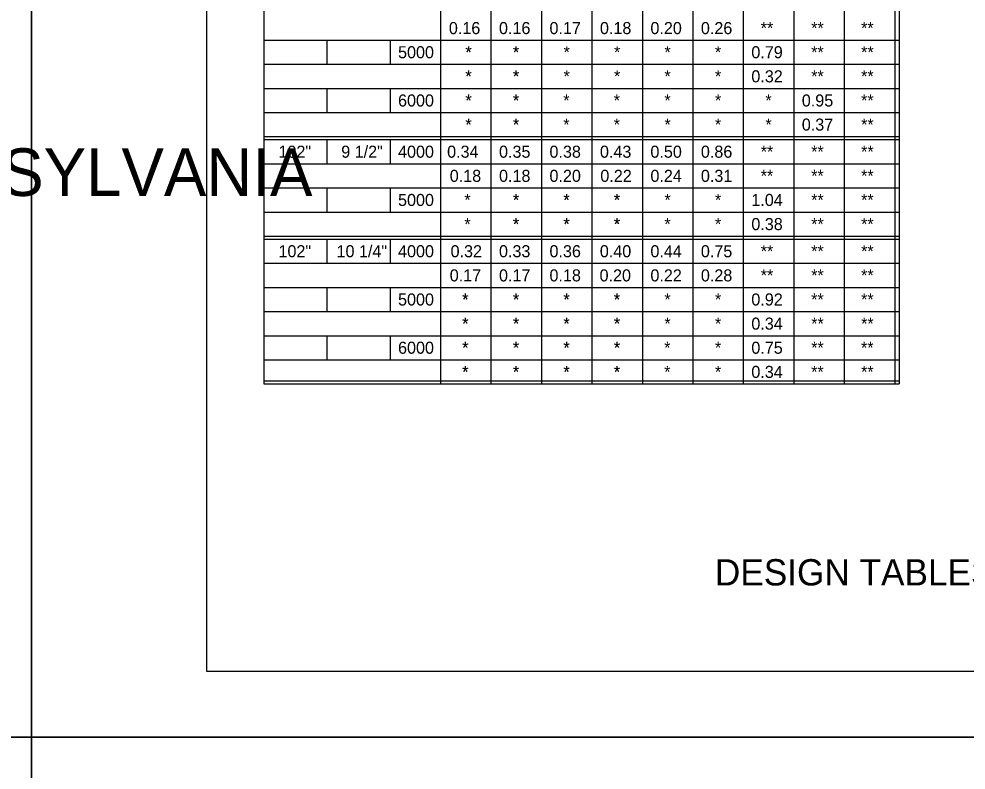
# Model space of a CAD drawing. Extents: x -22562 to -18409, y 3991 to 7171.
# Drawn here: x -20387.7 to -20171.7, y 5765.9 to 5937.3 of the extents above; entities that cross this region are included whole.
import ezdxf

# ---------------------------------------------------------------- set-up
doc = ezdxf.new("R2010")
doc.units = 0
for name, color, linetype in [('1', 7, 'Continuous'), ('2', 7, 'Continuous'), ('3', 7, 'Continuous'), ('4', 7, 'Continuous'), ('PLT-BNDY', 7, 'Continuous')]:
    doc.layers.add(name, color=color, linetype=linetype)

msp = doc.modelspace()

# ---------------------------------------------------------------- linework, layer by layer
at = {"layer": '2'}
for p, q in [((-20344.85, 5788.37), (-20344.85, 6352.37)), ((-20331.85, 6099.37), (-20331.85, 5853.98)), ((-20186.92, 6099.37), (-20186.92, 5853.98)), ((-20291.56, 6091.8), (-20291.56, 5853.98)), ((-20187.96, 6091.8), (-20187.96, 5853.98)), ((-20280.05, 6086.29), (-20280.05, 5853.98)), ((-20268.53, 6086.29), (-20268.53, 5853.98)), ((-20257.03, 6086.29), (-20257.03, 5853.98)), ((-20245.51, 6086.29), (-20245.51, 5853.98)), ((-20234, 6086.29), (-20234, 5853.98)), ((-20222.49, 6086.29), (-20222.49, 5853.98)), ((-20210.98, 6086.29), (-20210.98, 5853.98)), ((-20199.47, 6086.29), (-20199.47, 5853.98)), ((-20331.85, 5932.42), (-20186.92, 5932.42)), ((-20317.46, 5932.42), (-20317.46, 5926.92)), ((-20303.07, 5932.42), (-20303.07, 5926.92)), ((-20331.85, 5926.92), (-20186.92, 5926.92)), ((-20331.85, 5921.41), (-20186.92, 5921.41)), ((-20317.46, 5921.41), (-20317.46, 5915.91)), ((-20303.07, 5921.41), (-20303.07, 5915.91)), ((-20331.85, 5915.91), (-20186.92, 5915.91)), ((-20331.85, 5910.4), (-20186.92, 5910.4)), ((-20331.85, 5910.4), (-20186.92, 5910.4)), ((-20331.85, 5909.72), (-20186.92, 5909.72)), ((-20317.46, 5909.72), (-20317.46, 5904.21)), ((-20303.07, 5909.72), (-20303.07, 5904.21)), ((-20331.85, 5904.21), (-20186.92, 5904.21)), ((-20331.85, 5898.71), (-20186.92, 5898.71)), ((-20317.46, 5898.71), (-20317.46, 5893.2)), ((-20303.07, 5898.71), (-20303.07, 5893.2)), ((-20331.85, 5893.2), (-20186.92, 5893.2)), ((-20331.85, 5887.7), (-20186.92, 5887.7)), ((-20331.85, 5887.01), (-20186.92, 5887.01)), ((-20317.46, 5887.01), (-20317.46, 5881.5)), ((-20303.07, 5887.01), (-20303.07, 5881.5)), ((-20331.85, 5881.5), (-20186.92, 5881.5)), ((-20331.85, 5876), (-20186.92, 5876)), ((-20317.46, 5876), (-20317.46, 5870.49)), ((-20303.07, 5876), (-20303.07, 5870.49)), ((-20331.85, 5870.49), (-20186.92, 5870.49)), ((-20331.85, 5864.98), (-20186.92, 5864.98)), ((-20317.46, 5864.98), (-20317.46, 5859.48)), ((-20303.07, 5864.98), (-20303.07, 5859.48)), ((-20331.85, 5859.48), (-20186.92, 5859.48)), ((-20331.85, 5854.66), (-20186.92, 5854.66)), ((-20331.85, 5853.98), (-20186.92, 5853.98)), ((-19558.85, 5788.37), (-20344.85, 5788.37))]:
    msp.add_line(p, q, dxfattribs=at)
at = {"layer": 'PLT-BNDY'}
for points in [[(-21225.85, 6367.37), (-20384.85, 6367.37), (-20384.85, 5773.37), (-21225.85, 5773.37)], [(-20384.85, 6367.37), (-19543.85, 6367.37), (-19543.85, 5773.37), (-20384.85, 5773.37)], [(-21225.85, 5773.37), (-20384.85, 5773.37), (-20384.85, 5179.37), (-21225.85, 5179.37)], [(-20384.85, 5773.37), (-19543.85, 5773.37), (-19543.85, 5179.37), (-20384.85, 5179.37)]]:
    msp.add_lwpolyline(points, close=True, dxfattribs=at)

# ---------------------------------------------------------------- texts
at = {"layer": '1'}
for p in [(-20328.51, 5905.59), (-20328.51, 5882.88)]:
    msp.add_text('102"', height=2.751, dxfattribs=at).set_placement(p)
at = {"layer": '2'}
for s, height, p in [('COMMONWEALTH OF PENNSYLVANIA', 10.8525, (-20588.47, 5896.87)), ('DESIGN TABLES FOR CIRCULAR PIPES - TYPE A STANDARD INSTALLATION', 6, (-20228.97, 5807.99))]:
    msp.add_text(s, height=height, dxfattribs=at).set_placement(p)
at = {"layer": '3'}
for s, height, p in [('0.16', 2.753, (-20289.65, 5933.8)), ('0.16', 2.753, (-20278.22, 5933.8)), ('0.17', 2.753, (-20266.7, 5933.8)), ('0.18', 2.753, (-20255.19, 5933.8)), ('0.20', 2.753, (-20243.68, 5933.8)), ('0.26', 2.753, (-20232.17, 5933.8)), ('**', 2.753, (-20218.52, 5933.8)), ('**', 2.753, (-20207.01, 5933.8)), ('**', 2.751, (-20195.62, 5933.8)), ('*', 2.75, (-20285.91, 5928.29)), ('*', 2.75, (-20285.85, 5928.29)), ('*', 2.75, (-20275.07, 5928.29)), ('*', 2.75, (-20275.01, 5928.29)), ('*', 2.75, (-20263.49, 5928.29)), ('*', 2.75, (-20251.98, 5928.29)), ('*', 2.75, (-20240.48, 5928.29)), ('*', 2.75, (-20228.96, 5928.29)), ('0.79', 2.753, (-20220.66, 5928.29)), ('**', 2.753, (-20207.01, 5928.29)), ('**', 2.751, (-20195.62, 5928.29)), ('*', 2.75, (-20285.91, 5922.79)), ('*', 2.75, (-20285.85, 5922.79)), ('*', 2.75, (-20275.07, 5922.79)), ('*', 2.75, (-20275.01, 5922.79)), ('*', 2.75, (-20263.49, 5922.79)), ('*', 2.75, (-20251.98, 5922.79)), ('*', 2.75, (-20240.48, 5922.79)), ('*', 2.75, (-20228.96, 5922.79)), ('0.32', 2.753, (-20220.66, 5922.79)), ('**', 2.753, (-20207.01, 5922.79)), ('**', 2.751, (-20195.62, 5922.79)), ('*', 2.75, (-20285.91, 5917.28)), ('*', 2.75, (-20285.85, 5917.28)), ('*', 2.75, (-20275.07, 5917.28)), ('*', 2.75, (-20275.01, 5917.28)), ('*', 2.75, (-20263.56, 5917.28)), ('*', 2.75, (-20252.05, 5917.28)), ('*', 2.75, (-20240.48, 5917.28)), ('*', 2.75, (-20228.96, 5917.28)), ('*', 2.75, (-20217.45, 5917.28)), ('0.95', 2.753, (-20209.15, 5917.28)), ('**', 2.751, (-20195.62, 5917.28)), ('*', 2.75, (-20285.91, 5911.78)), ('*', 2.75, (-20285.85, 5911.78)), ('*', 2.75, (-20275.07, 5911.78)), ('*', 2.75, (-20275.01, 5911.78)), ('*', 2.75, (-20263.56, 5911.78)), ('*', 2.75, (-20252.05, 5911.78)), ('*', 2.75, (-20240.48, 5911.78)), ('*', 2.75, (-20228.96, 5911.78)), ('*', 2.75, (-20217.45, 5911.78)), ('0.37', 2.753, (-20209.15, 5911.78)), ('**', 2.751, (-20195.62, 5911.78)), ('0.34', 2.753, (-20290.05, 5905.59)), ('0.35', 2.753, (-20278.21, 5905.59)), ('0.38', 2.753, (-20266.7, 5905.59)), ('0.43', 2.753, (-20255.19, 5905.59)), ('0.50', 2.753, (-20243.68, 5905.59)), ('0.86', 2.753, (-20232.17, 5905.59)), ('**', 2.753, (-20218.52, 5905.59)), ('**', 2.753, (-20207.01, 5905.59)), ('**', 2.751, (-20195.62, 5905.59)), ('0.18', 2.753, (-20289.45, 5900.08)), ('0.18', 2.753, (-20278.21, 5900.08)), ('0.20', 2.753, (-20266.7, 5900.08)), ('0.22', 2.753, (-20255.1, 5900.08)), ('0.24', 2.753, (-20243.68, 5900.08)), ('0.31', 2.753, (-20232.17, 5900.08)), ('**', 2.753, (-20218.52, 5900.08)), ('**', 2.753, (-20207.01, 5900.08)), ('**', 2.751, (-20195.62, 5900.08)), ('1.04', 2.753, (-20220.66, 5894.58)), ('*', 2.75, (-20286.11, 5894.58)), ('*', 2.75, (-20275.07, 5894.58)), ('*', 2.75, (-20275.01, 5894.58)), ('*', 2.75, (-20263.56, 5894.58)), ('*', 2.75, (-20263.49, 5894.58)), ('*', 2.75, (-20252.05, 5894.58)), ('*', 2.75, (-20251.98, 5894.58)), ('*', 2.75, (-20240.48, 5894.58)), ('*', 2.75, (-20228.96, 5894.58)), ('**', 2.753, (-20207.01, 5894.58)), ('**', 2.751, (-20195.62, 5894.58)), ('*', 2.75, (-20286.11, 5889.05)), ('*', 2.75, (-20275.07, 5889.07)), ('*', 2.75, (-20275.01, 5889.07)), ('*', 2.75, (-20263.56, 5889.07)), ('*', 2.75, (-20263.49, 5889.07)), ('*', 2.75, (-20252.05, 5889.07)), ('*', 2.75, (-20251.98, 5889.07)), ('*', 2.75, (-20240.48, 5889.07)), ('*', 2.75, (-20228.96, 5889.07)), ('0.38', 2.753, (-20220.66, 5889.07)), ('**', 2.753, (-20207.01, 5889.07)), ('**', 2.751, (-20195.62, 5889.07)), ('0.32', 2.753, (-20289.26, 5882.88)), ('0.33', 2.753, (-20278.22, 5882.88)), ('0.36', 2.753, (-20266.7, 5882.88)), ('0.40', 2.753, (-20255.22, 5882.88)), ('0.44', 2.753, (-20243.68, 5882.88)), ('0.75', 2.753, (-20232.17, 5882.88)), ('**', 2.753, (-20218.52, 5882.88)), ('**', 2.753, (-20207.01, 5882.88)), ('**', 2.751, (-20195.62, 5882.87)), ('0.17', 2.753, (-20289.45, 5877.37)), ('0.17', 2.753, (-20278.21, 5877.37)), ('0.18', 2.753, (-20266.7, 5877.37)), ('0.20', 2.753, (-20255.28, 5877.37)), ('0.22', 2.753, (-20243.68, 5877.37)), ('0.28', 2.753, (-20232.17, 5877.37)), ('**', 2.753, (-20218.52, 5877.37)), ('**', 2.753, (-20207.01, 5877.37)), ('**', 2.751, (-20195.62, 5877.37)), ('*', 2.75, (-20286.64, 5871.87)), ('*', 2.75, (-20286.57, 5871.87)), ('*', 2.75, (-20275.07, 5871.87)), ('*', 2.75, (-20275.01, 5871.87)), ('*', 2.75, (-20263.56, 5871.87)), ('*', 2.75, (-20263.49, 5871.87)), ('*', 2.75, (-20252.05, 5871.87)), ('*', 2.75, (-20251.98, 5871.87)), ('*', 2.75, (-20240.48, 5871.87)), ('*', 2.75, (-20228.96, 5871.87)), ('0.92', 2.753, (-20220.66, 5871.87)), ('**', 2.753, (-20207.01, 5871.87)), ('**', 2.751, (-20195.62, 5871.87)), ('*', 2.75, (-20286.64, 5866.36)), ('*', 2.75, (-20286.57, 5866.36)), ('*', 2.75, (-20275.07, 5866.36)), ('*', 2.75, (-20275.01, 5866.36)), ('*', 2.75, (-20263.56, 5866.36)), ('*', 2.75, (-20263.49, 5866.36)), ('*', 2.75, (-20252.05, 5866.36)), ('*', 2.75, (-20251.98, 5866.36)), ('*', 2.75, (-20240.48, 5866.36)), ('*', 2.75, (-20228.96, 5866.36)), ('0.34', 2.753, (-20220.66, 5866.36)), ('**', 2.753, (-20207.01, 5866.36)), ('**', 2.751, (-20195.62, 5866.36)), ('*', 2.75, (-20286.64, 5860.86)), ('*', 2.75, (-20286.57, 5860.86)), ('*', 2.75, (-20275.07, 5860.86)), ('*', 2.75, (-20275.01, 5860.86)), ('*', 2.75, (-20263.56, 5860.86)), ('*', 2.75, (-20263.49, 5860.86)), ('*', 2.75, (-20252.05, 5860.86)), ('*', 2.75, (-20251.98, 5860.86)), ('*', 2.75, (-20240.54, 5860.86)), ('*', 2.75, (-20228.96, 5860.86)), ('0.75', 2.753, (-20220.66, 5860.86)), ('**', 2.753, (-20207.01, 5860.86)), ('*', 2.75, (-20286.64, 5855.35)), ('*', 2.75, (-20286.57, 5855.35)), ('*', 2.75, (-20275.07, 5855.35)), ('*', 2.75, (-20275.01, 5855.35)), ('*', 2.75, (-20263.56, 5855.35)), ('*', 2.75, (-20263.49, 5855.35)), ('*', 2.75, (-20252.05, 5855.35)), ('*', 2.75, (-20251.98, 5855.35)), ('*', 2.75, (-20240.54, 5855.35)), ('*', 2.75, (-20228.96, 5855.35)), ('0.34', 2.753, (-20220.66, 5855.35)), ('**', 2.753, (-20207.01, 5855.35))]:
    msp.add_text(s, height=height, dxfattribs=at).set_placement(p)
for rotation, p in [(0.7078, (-20195.62, 5860.84)), (0.2583, (-20195.62, 5855.34))]:
    msp.add_text('**', height=2.751, rotation=rotation, dxfattribs=at).set_placement(p)
at = {"layer": '4'}
for s, height, p in [('5000', 2.753, (-20301.24, 5928.29)), ('6000', 2.753, (-20301.24, 5917.28)), ('9 1/2"', 2.751, (-20314.2, 5905.59)), ('4000', 2.753, (-20301.24, 5905.59)), ('5000', 2.753, (-20301.24, 5894.58)), ('10 1/4"', 2.751, (-20315.27, 5882.88)), ('4000', 2.753, (-20301.24, 5882.88)), ('5000', 2.753, (-20301.24, 5871.87)), ('6000', 2.753, (-20301.24, 5860.86))]:
    msp.add_text(s, height=height, dxfattribs=at).set_placement(p)

doc.saveas('drawing.dxf')
